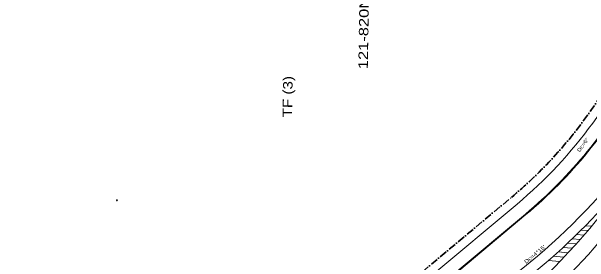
# Model space of a CAD drawing. Extents: x 2354993 to 2372084, y 6966390 to 6990057.
# Drawn here: x 2363006 to 2364225, y 6979100 to 6979630 of the extents above; entities that cross this region are included whole.
import ezdxf

# ---------------------------------------------------------------- set-up
doc = ezdxf.new("R2010")
doc.units = 0
doc.header["$LTSCALE"] = 3.2
doc.linetypes.add('DOT_DASHED', pattern=[7.7, 5, -1.2, 0.3, -1.2])
for name, color, linetype, lineweight in [('17', 7, 'Continuous', 13), ('25', 7, 'Continuous', 13), ('4', 7, 'Continuous', 13), ('5', 7, 'Continuous', 13), ('6', 7, 'Continuous', 13), ('63', 7, 'Continuous', 13), ('9', 7, 'Continuous', 13)]:
    doc.layers.add(name, color=color, linetype=linetype, lineweight=lineweight)

msp = doc.modelspace()

# ---------------------------------------------------------------- linework, layer by layer
at = {"layer": '25'}
for p, q in [((2363229.804, 6979231.195), (2363226.304, 6979231.195)), ((2363228.054, 6979232.945), (2363228.054, 6979229.445)), ((2363695.384, 6978907.983), (2364072.128, 6979223.133)), ((2363911.877, 6979053.229), (2364089.77, 6979202.039)), ((2363912.839, 6979052.078), (2364090.732, 6979200.888))]:
    msp.add_line(p, q, dxfattribs=at)
for centre, radius, start, end in [((2363460.388, 6979954.434), 953.429, 309.91281, 338.11957), ((2363460.389, 6979954.435), 980.929, 309.91253, 331.65955), ((2363460.389, 6979954.435), 982.429, 309.91253, 331.65955), ((2362792.03, 6980397.363), 1885.859, 301.04574, 322.89258), ((2363247.127, 6980134.169), 1362.136, 297.46364, 320.4266)]:
    msp.add_arc(centre, radius, start, end, dxfattribs=at)
at = {"layer": '4'}
for p, q in [((2364169.006, 6979131.395), (2364188.329, 6979129.761)), ((2364148.639, 6979113.046), (2364171.194, 6979111.139)), ((2364159.109, 6979122.195), (2364179.814, 6979120.444)), ((2364138.169, 6979103.897), (2364162.465, 6979101.843))]:
    msp.add_line(p, q, dxfattribs=at)
for centre, radius, start, end in [((2363247.127, 6980134.169), 1340.136, 297.46364, 325.00264), ((2362792.03, 6980397.361), 1919.859, 305.78394, 323.02193)]:
    msp.add_arc(centre, radius, start, end, dxfattribs=at)
at = {"layer": '5'}
for p, q in [((2364216.798, 6979177.532), (2364229.349, 6979176.471)), ((2364207.578, 6979168.276), (2364221.346, 6979167.111)), ((2364189.442, 6979149.738), (2364205.042, 6979148.419)), ((2364198.193, 6979159.034), (2364213.245, 6979157.761)), ((2364179.34, 6979140.558), (2364196.737, 6979139.086))]:
    msp.add_line(p, q, dxfattribs=at)
at = {"layer": '6', "linetype": 'DOT_DASHED', "lineweight": 35}
msp.add_line((2363683.514, 6978922.173), (2364060.258, 6979237.323), dxfattribs=at)
msp.add_arc((2363460.388, 6979954.434), 934.929, 309.91281, 338.11957, dxfattribs=at)
at = {"layer": '9'}
msp.add_arc((2360722.521, 6984327.136), 5729.573, 359.50797, 359.50797, dxfattribs=at)

# ---------------------------------------------------------------- texts
at = {"layer": '17'}
for s, rotation, width, p in [('Dc=6°', 54.089, 1.15, (2364204.455, 6979332.053)), ("Dc=4°15'", 39.192, 1.25, (2364091.184, 6979096.857))]:
    msp.add_text(s, height=8, rotation=rotation, dxfattribs=dict(at, width=width)).set_placement(p)
at = {"layer": '63'}
for s, width, p in [('121-820N (4 & 5)', 1.3, (2363757.245, 6979507.779)), ('TF (3)', 1.2, (2363597.374, 6979406.075))]:
    msp.add_text(s, height=20, rotation=89.044, dxfattribs=dict(at, width=width)).set_placement(p)

doc.saveas('drawing.dxf')
